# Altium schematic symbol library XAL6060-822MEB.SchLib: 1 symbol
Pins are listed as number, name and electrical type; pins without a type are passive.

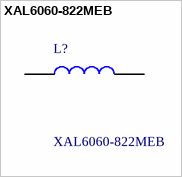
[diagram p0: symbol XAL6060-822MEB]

## XAL6060-822MEB
designator L?
Fixed Inductors XAL6060 High Current 8.2 uH 20 % 8 A; Manufacturer_Name: COILCRAFT; Geometry.Height: 6.1mm
footprint XAL6060822MEB
pins: 1, 2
